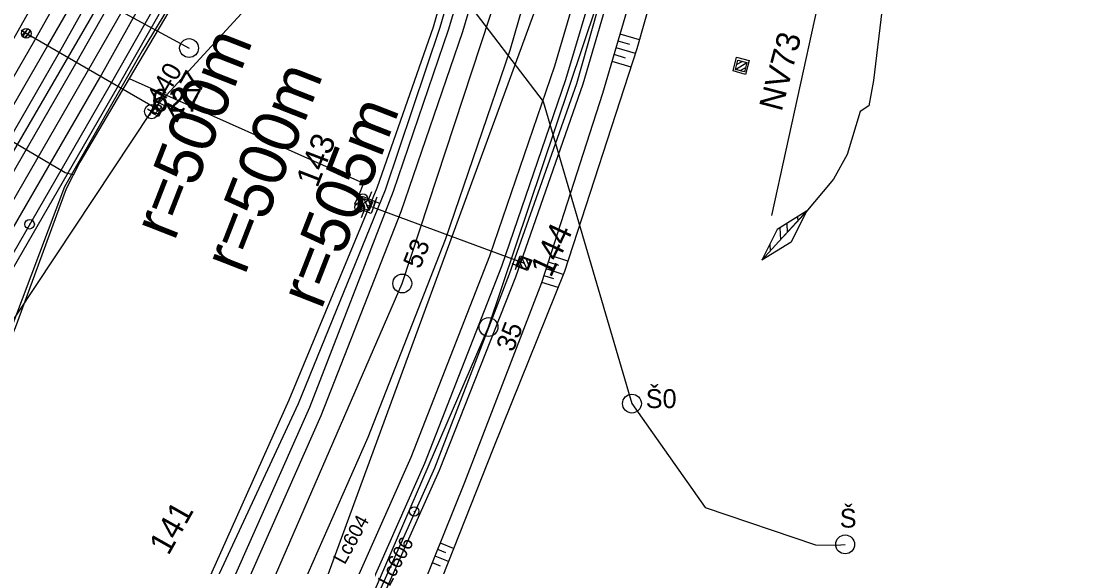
# Model space of a CAD drawing. Extents: x -598638 to -597933, y -1164002 to -1161904.
# Drawn here: x -598318.5 to -598207, y -1163482.9 to -1163425.1 of the extents above; entities that cross this region are included whole.
import ezdxf

# ---------------------------------------------------------------- set-up
doc = ezdxf.new("R2010")
doc.units = 0
for name, color, linetype in [('Vrstva 1', 7, 'Continuous'), ('Vrstva 11', 7, 'Continuous'), ('Vrstva 12', 7, 'Continuous'), ('Vrstva 25', 7, 'Continuous'), ('Vrstva 26', 7, 'Continuous'), ('Vrstva 28', 7, 'Continuous'), ('Vrstva 31', 7, 'Continuous'), ('Vrstva 4', 7, 'Continuous'), ('Vrstva 43', 7, 'Continuous'), ('Vrstva 44', 7, 'Continuous'), ('Vrstva 48', 7, 'Continuous'), ('Vrstva 49', 7, 'Continuous'), ('Vrstva 51', 7, 'Continuous'), ('Vrstva 6', 7, 'Continuous'), ('Vrstva 63', 7, 'Continuous'), ('Vrstva 7', 7, 'Continuous')]:
    doc.layers.add(name, color=color, linetype=linetype)

msp = doc.modelspace()

# ---------------------------------------------------------------- linework, layer by layer
at = {"layer": 'Vrstva 1'}
for points in [[(-598301.84, -1163499.63), (-598294.73, -1163484.99), (-598286.72, -1163466.88), (-598278.24, -1163445.24), (-598271.7, -1163426.18), (-598265.18, -1163404.08), (-598264.28, -1163400.72)], [(-598295.82, -1163499.94), (-598294.22, -1163496.62), (-598290.23, -1163488.37), (-598281.74, -1163469.16), (-598273.54, -1163448.2), (-598266.68, -1163428.14), (-598259.16, -1163402.07)], [(-598291.35, -1163502.18), (-598289.74, -1163498.85), (-598285.79, -1163490.68), (-598277.19, -1163471.28), (-598268.83, -1163449.93), (-598261.94, -1163429.79), (-598255.59, -1163408.17), (-598254.29, -1163403.3)], [(-598390.95, -1163558.18), (-598390.16, -1163556.81), (-598368.81, -1163519.75), (-598341.41, -1163472.23), (-598315.71, -1163427.65), (-598306.31, -1163411.35)], [(-598386.66, -1163560.82), (-598364.21, -1163521.84), (-598337.05, -1163474.72), (-598311.51, -1163430.39), (-598301.88, -1163413.66)]]:
    msp.add_lwpolyline(points, dxfattribs=at)
at = {"layer": 'Vrstva 11'}
for p, q in [((-598318.44, -1163426.54), (-598317.8, -1163425.9)), ((-598318.18, -1163426.81), (-598317.53, -1163426.16)), ((-598242.67, -1163429.66), (-598242.1, -1163429.33)), ((-598242.8, -1163430.18), (-598241.58, -1163429.46)), ((-598242.29, -1163430.31), (-598241.71, -1163429.97)), ((-598304.58, -1163434.59), (-598303.94, -1163433.95)), ((-598304.32, -1163434.86), (-598303.67, -1163434.21)), ((-598281.64, -1163445.16), (-598282.17, -1163443.89)), ((-598281.73, -1163444.08), (-598281.35, -1163443.14)), ((-598282.11, -1163444.99), (-598282.49, -1163445.92)), ((-598282.11, -1163444.99), (-598282.39, -1163444.35)), ((-598281.44, -1163444.67), (-598281.68, -1163444.09)), ((-598265.69, -1163450.58), (-598265.41, -1163451.19)), ((-598265.49, -1163450.08), (-598264.92, -1163451.37)), ((-598265, -1163450.28), (-598264.73, -1163450.88))]:
    msp.add_line(p, q, dxfattribs=at)
for points in [[(-598304.12, -1163434.41), (-598317.98, -1163426.36)], [(-598242.55, -1163429.21), (-598241.58, -1163429.46), (-598241.83, -1163430.43), (-598242.8, -1163430.18), (-598242.55, -1163429.21)], [(-598282.57, -1163444.8), (-598282.19, -1163443.88), (-598281.27, -1163444.26), (-598281.65, -1163445.18), (-598282.57, -1163444.8)], [(-598281.92, -1163444.53), (-598265.21, -1163450.73)], [(-598264.56, -1163450.44), (-598264.92, -1163451.38), (-598265.86, -1163451.02), (-598265.5, -1163450.08), (-598264.56, -1163450.44)]]:
    msp.add_lwpolyline(points, dxfattribs=at)
for points in [[(-598242.55, -1163429.21), (-598241.58, -1163429.46), (-598241.83, -1163430.43), (-598242.8, -1163430.18)], [(-598282.57, -1163444.8), (-598282.19, -1163443.88), (-598281.27, -1163444.26), (-598281.65, -1163445.18)], [(-598264.56, -1163450.44), (-598264.92, -1163451.38), (-598265.86, -1163451.02), (-598265.5, -1163450.08)]]:
    msp.add_lwpolyline(points, close=True, dxfattribs=at)
for centre in [(-598317.98, -1163426.36), (-598304.12, -1163434.41)]:
    msp.add_circle(centre, 0.5, dxfattribs=at)
at = {"layer": 'Vrstva 12'}
for points in [[(-598243.05, -1163430.35), (-598242.67, -1163428.9), (-598241.36, -1163429.24), (-598241.74, -1163430.71), (-598243.05, -1163430.35)], [(-598304.81, -1163434.73), (-598304.17, -1163433.58), (-598303.33, -1163434.02), (-598303.95, -1163435.19), (-598304.81, -1163434.73)], [(-598280.95, -1163444.19), (-598281.41, -1163445.44), (-598282.87, -1163444.88), (-598282.36, -1163443.63), (-598280.95, -1163444.19)], [(-598266.06, -1163451.04), (-598265.64, -1163449.95), (-598264.4, -1163450.41), (-598264.83, -1163451.49), (-598266.06, -1163451.04)]]:
    msp.add_lwpolyline(points, dxfattribs=at)
at = {"layer": 'Vrstva 25'}
for p, q in [((-598282.34, -1163443.88), (-598282.24, -1163443.88)), ((-598282.69, -1163444.8), (-598282.59, -1163444.8))]:
    msp.add_line(p, q, dxfattribs=at)
for centre in [(-598282.3, -1163443.88), (-598282.64, -1163444.8)]:
    msp.add_circle(centre, 0.5, dxfattribs=at)
at = {"layer": 'Vrstva 26'}
for points in [[(-598273.82, -1163355.58), (-598274.29, -1163357.58), (-598281.23, -1163380.7), (-598286.2, -1163393.22), (-598294.19, -1163409.28), (-598301.29, -1163421.31), (-598307.09, -1163431.14)], [(-598307.09, -1163431.14), (-598312.31, -1163440), (-598313.75, -1163442.83), (-598319.17, -1163457.57), (-598329.12, -1163481.28), (-598331.17, -1163484.85), (-598341.64, -1163499.88), (-598347.26, -1163507.65), (-598355.17, -1163519.01), (-598361.01, -1163527.07), (-598366.38, -1163535.86), (-598371.61, -1163544.14), (-598378.91, -1163556.09), (-598381.71, -1163561.13), (-598385.12, -1163568.37), (-598389.63, -1163576.94), (-598393, -1163584.21), (-598395.85, -1163591.65), (-598398.96, -1163599.02), (-598402.34, -1163608.48), (-598403.43, -1163608.3), (-598416.74, -1163603.14), (-598417.16, -1163603)], [(-598307.09, -1163431.14), (-598282.23, -1163442.23), (-598282.76, -1163443.57), (-598283.17, -1163444.47), (-598282.75, -1163444.54), (-598282.64, -1163444.8)], [(-598313.02, -1163441.37), (-598313.85, -1163441.13), (-598323.22, -1163435.65)], [(-598282.76, -1163443.57), (-598282.42, -1163443.66), (-598282.3, -1163443.88)]]:
    msp.add_lwpolyline(points, dxfattribs=at)
at = {"layer": 'Vrstva 28'}
msp.add_lwpolyline([(-598299.13, -1163417.38), (-598305.71, -1163428.21), (-598313.95, -1163442.64), (-598320.15, -1163459.12), (-598330, -1163482.52), (-598335.96, -1163491.26), (-598347.35, -1163507.42), (-598355.33, -1163518.86), (-598362.35, -1163528.57), (-598373.82, -1163547.05), (-598380.92, -1163559.06), (-598385.36, -1163568.33)], dxfattribs=at)
at = {"layer": 'Vrstva 31'}
for p, q in [((-598236.22, -1163445.81), (-598236.2, -1163446.27)), ((-598235.5, -1163445.39), (-598235.52, -1163445.52)), ((-598238.08, -1163446.97), (-598238.02, -1163448.25)), ((-598237.35, -1163446.5), (-598237.31, -1163447.47)), ((-598239.16, -1163448.69), (-598239.12, -1163449.46)), ((-598239.82, -1163450.06), (-598239.81, -1163450.21))]:
    msp.add_line(p, q, dxfattribs=at)
for points in [[(-598220.13, -1163364.15), (-598222.21, -1163370.93), (-598223.12, -1163377.98), (-598223.32, -1163382.98), (-598222.87, -1163386.04), (-598223.18, -1163389.86), (-598224.37, -1163399.35), (-598225.44, -1163407.84), (-598226.45, -1163415.61), (-598227.16, -1163423.11), (-598228.16, -1163431.35), (-598228.66, -1163434.06), (-598229.57, -1163434.64), (-598230.96, -1163439.2), (-598232.42, -1163441.82), (-598235.52, -1163445.52), (-598237.63, -1163447.82)], [(-598235.25, -1163445.22), (-598236.88, -1163448.51), (-598240, -1163450.42)]]:
    msp.add_lwpolyline(points, dxfattribs=at)
msp.add_lwpolyline([(-598235.25, -1163445.22), (-598238.38, -1163447.14), (-598240, -1163450.42)], close=True, dxfattribs=at)
at = {"layer": 'Vrstva 4'}
for points in [[(-598321.68, -1163563.95), (-598314.65, -1163552.34), (-598302.07, -1163529.78), (-598292.77, -1163512.02), (-598281.73, -1163489.57), (-598274.16, -1163472.67), (-598266.07, -1163452.17), (-598258.95, -1163431.71), (-598252.67, -1163410.24), (-598246.46, -1163386.1), (-598243.14, -1163368.88), (-598239.95, -1163345.76), (-598237.56, -1163323.25), (-598236.68, -1163305.47), (-598236.28, -1163282.74), (-598236.43, -1163244.57), (-598236.6, -1163214.62), (-598236.87, -1163174.88), (-598236.23, -1163131.24), (-598234.78, -1163108.25), (-598234.29, -1163099.46), (-598231.79, -1163078.34)], [(-598283.36, -1163489.15), (-598275.74, -1163471.92), (-598267.55, -1163451.03), (-598260.79, -1163431.26), (-598254.34, -1163409.72), (-598248.47, -1163385.64), (-598245.05, -1163368.35), (-598241.71, -1163345.6), (-598239.46, -1163322.75), (-598238.48, -1163305.47), (-598238.2, -1163283.28), (-598238.41, -1163245.16), (-598238.38, -1163215.17), (-598238.53, -1163175.26), (-598238.39, -1163131.33), (-598237.2, -1163108.68), (-598236.12, -1163097.62), (-598233.74, -1163078.21)], [(-598307.38, -1163503.64), (-598306.26, -1163500.72), (-598304.53, -1163496.74), (-598299.48, -1163486.14), (-598290.12, -1163465.2), (-598280.8, -1163442.72), (-598274.81, -1163425.66), (-598269.09, -1163405.62), (-598262.91, -1163380.49), (-598260.22, -1163366.07), (-598256.64, -1163342.66), (-598254.61, -1163322.43), (-598252.98, -1163304.93), (-598251.44, -1163287.27), (-598250.07, -1163266.22), (-598248.82, -1163245.45), (-598248.47, -1163214.54), (-598248.62, -1163173.63), (-598248.07, -1163131.25), (-598247.6, -1163128.35)], [(-598388.69, -1163572.82), (-598382.7, -1163561.09), (-598361.38, -1163524.29), (-598334.6, -1163477.58), (-598308.35, -1163432.12), (-598292.47, -1163404.26), (-598285.94, -1163390.16), (-598281.63, -1163378.65), (-598277.22, -1163365.01), (-598272.58, -1163348.28), (-598269.39, -1163336.75), (-598267.11, -1163324.87), (-598262.67, -1163291.92), (-598258.64, -1163259.14), (-598254.18, -1163220.99), (-598251.65, -1163201.07), (-598250.77, -1163187.5), (-598249.67, -1163144.52), (-598248.92, -1163130.78), (-598248.69, -1163130.31)]]:
    msp.add_lwpolyline(points, dxfattribs=at)
at = {"layer": 'Vrstva 43'}
for centre in [(-598300.73, -1163427.92), (-598278.12, -1163452.87), (-598268.98, -1163457.49), (-598253.77, -1163465.61), (-598231.17, -1163480.53)]:
    msp.add_circle(centre, 1, dxfattribs=at)
at = {"layer": 'Vrstva 44'}
for points in [[(-598295.76, -1163493.48), (-598278.12, -1163452.87), (-598264.21, -1163410.56), (-598254.47, -1163367.19), (-598248.62, -1163321.58), (-598253.5, -1163320.89), (-598249.61, -1163272.58), (-598247.64, -1163222.48), (-598247.49, -1163176.78), (-598247.44, -1163130.15), (-598244.01, -1163084.17), (-598235.33, -1163037.76), (-598224.82, -1163002.56), (-598219.38, -1163002.17), (-598206.65, -1162968.49), (-598191.4, -1162936.05), (-598173.75, -1162904.51), (-598155.69, -1162873.08), (-598136.14, -1162838.45), (-598116.78, -1162804.2)], [(-598286.82, -1163498.79), (-598268.98, -1163457.49), (-598254.68, -1163414.9), (-598244.49, -1163370.7), (-598238.63, -1163323.59), (-598237.18, -1163277.39), (-598237.39, -1163227.4), (-598237.55, -1163176.84), (-598237.22, -1163130.35), (-598233.36, -1163084.01), (-598224.14, -1163038.36), (-598215.27, -1163005.58), (-598224.82, -1163002.56)], [(-598403.64, -1163432.34), (-598346.56, -1163418.58), (-598345.22, -1163418.65), (-598343.66, -1163418.37), (-598342.1, -1163418.16), (-598292.97, -1163414.35), (-598291.23, -1163414.37), (-598274.65, -1163418.56), (-598263.2, -1163433.57), (-598253.77, -1163465.61), (-598253.12, -1163466.54), (-598246, -1163476.61), (-598234.31, -1163480.57), (-598232.07, -1163480.6), (-598231.17, -1163480.53)], [(-598351.58, -1163494.88), (-598326.62, -1163451.36), (-598310.06, -1163422.88), (-598300.73, -1163427.92)]]:
    msp.add_lwpolyline(points, dxfattribs=at)
at = {"layer": 'Vrstva 48'}
for p, q in [((-598252.97, -1163427.06), (-598255.02, -1163426.46)), ((-598253.4, -1163428.5), (-598255.44, -1163427.9)), ((-598254, -1163427.54), (-598255.23, -1163427.18)), ((-598253.86, -1163429.93), (-598255.86, -1163429.34)), ((-598254.44, -1163428.98), (-598255.65, -1163428.62)), ((-598260.56, -1163450.5), (-598262.4, -1163449.91)), ((-598261.05, -1163451.92), (-598262.86, -1163451.33)), ((-598261.53, -1163450.98), (-598262.63, -1163450.62)), ((-598261.61, -1163453.31), (-598263.33, -1163452.76)), ((-598262.04, -1163452.39), (-598263.09, -1163452.05)), ((-598272.68, -1163480.96), (-598274.08, -1163480.39)), ((-598273.23, -1163482.35), (-598274.64, -1163481.78)), ((-598273.52, -1163481.43), (-598274.36, -1163481.08)), ((-598274.07, -1163482.82), (-598274.92, -1163482.47))]:
    msp.add_line(p, q, dxfattribs=at)
at = {"layer": 'Vrstva 49'}
for points in [[(-598312.32, -1163561.93), (-598312.05, -1163560.13), (-598297.72, -1163533.78), (-598287.56, -1163512.38), (-598279.16, -1163492.97), (-598271.48, -1163473.93), (-598263.33, -1163452.77), (-598256.85, -1163432.71), (-598250.45, -1163410.89), (-598244.79, -1163386.29), (-598240.76, -1163366.99), (-598236.94, -1163346.43), (-598233.73, -1163325.76), (-598232.23, -1163311.78)], [(-598232.23, -1163311.78), (-598233.09, -1163326.31), (-598236.12, -1163345.21), (-598237.45, -1163358.35), (-598243.27, -1163388.29), (-598247.56, -1163407.94), (-598253.24, -1163428.02), (-598260.92, -1163451.59), (-598268.49, -1163470.38), (-598277.5, -1163493.17), (-598288.56, -1163518.33), (-598296.05, -1163535.04), (-598302.04, -1163547.93), (-598308.08, -1163558.09)], [(-598218.98, -1163327.15), (-598221.29, -1163348.51), (-598225.92, -1163376.81), (-598231.39, -1163411.01), (-598238.96, -1163445.68)]]:
    msp.add_lwpolyline(points, dxfattribs=at)
at = {"layer": 'Vrstva 51'}
for points in [[(-598384.98, -1163560.82), (-598363.18, -1163523.06), (-598335.95, -1163475.58), (-598310.18, -1163431.07), (-598295.15, -1163404.14), (-598288.46, -1163389.58), (-598283.96, -1163377.81), (-598279.77, -1163364.47), (-598275.2, -1163348.33), (-598271.93, -1163336.2), (-598269.31, -1163324.27), (-598265.08, -1163292.03), (-598261.05, -1163259.68), (-598256.1, -1163220.3), (-598254.43, -1163201.67), (-598253.67, -1163187.94), (-598252.02, -1163143.49), (-598251.53, -1163128.86), (-598250.79, -1163109), (-598250.07, -1163094.38), (-598248.22, -1163076.73)], [(-598305.92, -1163504.28), (-598297.33, -1163487.14), (-598287.92, -1163465.98), (-598279.04, -1163443.1), (-598273.21, -1163425.98), (-598267.2, -1163406.11), (-598261.01, -1163380.89), (-598258.17, -1163366.3), (-598254.57, -1163343.14), (-598252.44, -1163322.08), (-598250.96, -1163305.05), (-598249.49, -1163286.13), (-598247.96, -1163266.79), (-598246.72, -1163245.4), (-598246.64, -1163214.42), (-598246.63, -1163173.75), (-598246.35, -1163129.42), (-598245.48, -1163112.94), (-598244.08, -1163096.67), (-598241.47, -1163076.86)], [(-598298.89, -1163486.59), (-598289.11, -1163465.58), (-598279.91, -1163442.96), (-598274.11, -1163425.7), (-598268.27, -1163405.76), (-598262.24, -1163380.6), (-598259.7, -1163366.46), (-598256, -1163342.85), (-598253.86, -1163322.32), (-598252.41, -1163304.61), (-598250.98, -1163286.31), (-598249.46, -1163266.6), (-598248.13, -1163245.45), (-598247.96, -1163214.31), (-598248.01, -1163173.78), (-598247.47, -1163130.65), (-598247.6, -1163128.35), (-598246.69, -1163112.87), (-598245.18, -1163096.51), (-598242.92, -1163076.62)], [(-598389.42, -1163572.47), (-598383.24, -1163561.02), (-598361.93, -1163523.99), (-598335.34, -1163477.36), (-598309.07, -1163431.8), (-598293.63, -1163404.64), (-598286.92, -1163390.08), (-598282.52, -1163378.36), (-598278.25, -1163364.66), (-598273.76, -1163348.56), (-598270.37, -1163336.66), (-598267.89, -1163324.62), (-598263.66, -1163291.86), (-598259.72, -1163259.57), (-598255.01, -1163220.52), (-598252.86, -1163201.2), (-598252.03, -1163187.94), (-598250.64, -1163143.8), (-598250.02, -1163129.24), (-598249.18, -1163109.08), (-598248.42, -1163094.48), (-598246.69, -1163077.09)], [(-598282.31, -1163489.48), (-598274.67, -1163472.41), (-598266.77, -1163451.85), (-598259.62, -1163431.68), (-598253.51, -1163410.04), (-598247.11, -1163385.98), (-598243.85, -1163368.94), (-598240.56, -1163345.64), (-598238.08, -1163322.67), (-598237.34, -1163305.45), (-598236.8, -1163282.91), (-598237.05, -1163244.83), (-598237.3, -1163214.83), (-598237.44, -1163175.2), (-598237.17, -1163131.22), (-598235.77, -1163108.63), (-598234.98, -1163097.82), (-598232.53, -1163078.41)], [(-598405.75, -1163584.86), (-598406.57, -1163584.53), (-598399.62, -1163567.58), (-598392.99, -1163554.62), (-598370.64, -1163515.91), (-598344.59, -1163470.69), (-598318.97, -1163426.35), (-598303.98, -1163399.63), (-598297.88, -1163386.42), (-598293.24, -1163374.41), (-598289.08, -1163361.08), (-598284.44, -1163344.62), (-598278.42, -1163323.5), (-598273.78, -1163306.93), (-598268.86, -1163289.08)], [(-598405.75, -1163584.86), (-598398.06, -1163568.29), (-598390.91, -1163555.15), (-598369.15, -1163517.53), (-598342.95, -1163471.89), (-598317.09, -1163427.1), (-598302.09, -1163400.44), (-598295.93, -1163387.04), (-598291.26, -1163374.84), (-598287.22, -1163361.86), (-598282.44, -1163344.93), (-598276.55, -1163323.98), (-598272.02, -1163307.74), (-598269.63, -1163298.16), (-598267.96, -1163289.28), (-598268.86, -1163289.08)], [(-598427.32, -1163664.7), (-598428.18, -1163664.39), (-598425.64, -1163654.61), (-598418.44, -1163627.4), (-598410.12, -1163604.12), (-598400.96, -1163581.08), (-598395.46, -1163569.59), (-598389.92, -1163559.34), (-598367.42, -1163520.24), (-598340.12, -1163472.9), (-598314.46, -1163428.34), (-598299.48, -1163401.61), (-598293.18, -1163387.86), (-598288.58, -1163375.92), (-598284.45, -1163362.71), (-598279.88, -1163346.37), (-598272.89, -1163321.8)], [(-598427.32, -1163664.7), (-598423.95, -1163654.67), (-598416.39, -1163628.21), (-598407.71, -1163605.19), (-598398.5, -1163582.12), (-598393.55, -1163570.61), (-598388.11, -1163560.38), (-598365.54, -1163521.22), (-598338.35, -1163474.01), (-598312.73, -1163429.55), (-598297.64, -1163402.9), (-598291.21, -1163388.73), (-598286.7, -1163376.83), (-598282.47, -1163363.33), (-598277.87, -1163346.94), (-598274.73, -1163335.65), (-598271.96, -1163322.06), (-598272.89, -1163321.8)]]:
    msp.add_lwpolyline(points, dxfattribs=at)
at = {"layer": 'Vrstva 63'}
for p, q in [((-598304.7, -1163434.65), (-598243.44, -1163367.74)), ((-598303.78, -1163532.29), (-598243.44, -1163367.74)), ((-598415.7, -1163601.66), (-598304.7, -1163434.65)), ((-598304.75, -1163434.65), (-598304.65, -1163434.65))]:
    msp.add_line(p, q, dxfattribs=at)
msp.add_circle((-598304.7, -1163434.65), 0.756, dxfattribs=at)
at = {"layer": 'Vrstva 7'}
for p, q in [((-598317.69, -1163426.57), (-598318.54, -1163426.05)), ((-598317.85, -1163425.89), (-598318.38, -1163426.74)), ((-598317.56, -1163426.03), (-598318.1, -1163426.88)), ((-598318.25, -1163426.19), (-598317.41, -1163426.72)), ((-598304.27, -1163434.91), (-598305.13, -1163434.4)), ((-598304.45, -1163434.22), (-598304.96, -1163435.08)), ((-598280.82, -1163443.72), (-598281.18, -1163444.65)), ((-598281.47, -1163444), (-598280.54, -1163444.36)), ((-598317.68, -1163446.6), (-598317.58, -1163446.6)), ((-598265.83, -1163450.5), (-598266.17, -1163451.44)), ((-598265.53, -1163451.14), (-598266.47, -1163450.8)), ((-598276.91, -1163477.04), (-598276.81, -1163477.04))]:
    msp.add_line(p, q, dxfattribs=at)
for centre in [(-598317.63, -1163446.6), (-598276.86, -1163477.04)]:
    msp.add_circle(centre, 0.5, dxfattribs=at)

# ---------------------------------------------------------------- texts
at = {"layer": 'Vrstva 1'}
for s, rotation, p in [('r=500m', 68.6028, (-598302.28, -1163448.47)), ('r=500m', 68.6387, (-598294.81, -1163452.07)), ('r=505m', 68.6204, (-598286.71, -1163455.74))]:
    msp.add_text(s, height=5, rotation=rotation, dxfattribs=at).set_placement(p)
at = {"layer": 'Vrstva 11'}
for s, rotation, p in [('NV73', 75.2867, (-598237.91, -1163434.73)), ('427', 61.1532, (-598301.5, -1163436.16)), ('143', 68.9152, (-598287.13, -1163442.82)), ('144', 64.9831, (-598262.37, -1163452.34)), ('141', 60.4612, (-598302.92, -1163481.79))]:
    msp.add_text(s, height=2.5, rotation=rotation, dxfattribs=at).set_placement(p)
at = {"layer": 'Vrstva 43'}
for s, rotation, p in [('440', 60.0563, (-598303.61, -1163434.11)), ('53', 68.6387, (-598276.24, -1163451.43)), ('35', 68.6204, (-598266.38, -1163460.23))]:
    msp.add_text(s, height=2, rotation=rotation, dxfattribs=at).set_placement(p)
for s, p in [('Š0', (-598252.31, -1163466.08)), ('Š', (-598231.74, -1163478.75))]:
    msp.add_text(s, height=2, dxfattribs=at).set_placement(p)
at = {"layer": 'Vrstva 6'}
for s, p in [('Lc604', (-598284.22, -1163482.75)), ('Lc606', (-598279.49, -1163485.08))]:
    msp.add_text(s, height=1.5, rotation=61.2664, dxfattribs=at).set_placement(p)
at = {"layer": 'Vrstva 63'}
msp.add_text('627', height=2.4, dxfattribs=at).set_placement((-598304.7, -1163434.65))

doc.saveas('drawing.dxf')
